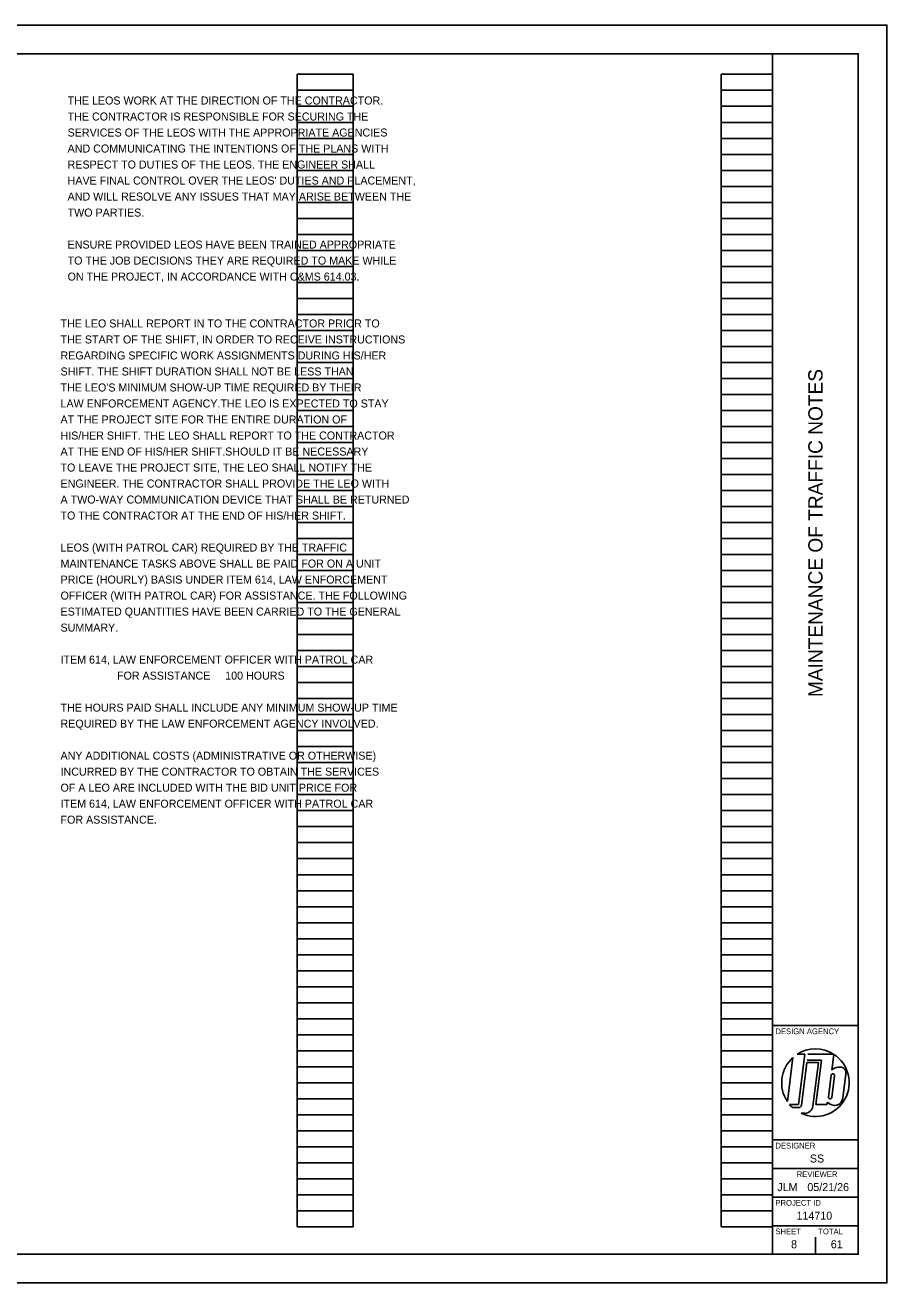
# Model space of a CAD drawing. Extents: x 0 to 34, y 0 to 22.
# Drawn here: x 18.92 to 34, y 0 to 22 of the extents above; entities that cross this region are included whole.
import ezdxf

# ---------------------------------------------------------------- set-up
doc = ezdxf.new("R2010")
doc.units = 0
for name, color, linetype in [('SH_Border', 7, 'Continuous'), ('SH_Cut_Line', 7, 'Continuous'), ('SH_Data', 7, 'Continuous'), ('SH_Text', 7, 'Continuous')]:
    doc.layers.add(name, color=color, linetype=linetype)

msp = doc.modelspace()

# ---------------------------------------------------------------- linework, layer by layer
at = {"layer": 'SH_Border'}
for p, q in [((32, 0.5), (32, 21.5)), ((32, 4.5), (33.5, 4.5)), ((32, 2.5), (33.5, 2.5)), ((32, 2), (33.5, 2)), ((32, 1.5), (33.5, 1.5)), ((32, 1), (33.5, 1))]:
    msp.add_line(p, q, dxfattribs=at)
msp.add_lwpolyline([(1.5, 21.5), (33.5, 21.5), (33.5, 0.5), (1.5, 0.5)], close=True, dxfattribs=at)
at = {"layer": 'SH_Cut_Line'}
msp.add_lwpolyline([(0, 0), (34, 0), (34, 22), (0, 22)], close=True, dxfattribs=at)
at = {"layer": 'SH_Data'}
for p, q in [((23.68, 0.98), (23.68, 21.14)), ((23.68, 21.14), (24.66, 21.14)), ((24.66, 0.98), (24.66, 21.14)), ((31.1, 0.98), (31.1, 21.14)), ((31.1, 21.14), (32, 21.14)), ((32, 0.98), (32, 21.14)), ((23.68, 20.86), (24.66, 20.86)), ((31.1, 20.86), (32, 20.86)), ((23.68, 20.58), (24.66, 20.58)), ((31.1, 20.58), (32, 20.58)), ((23.68, 20.3), (24.66, 20.3)), ((31.1, 20.3), (32, 20.3)), ((23.68, 20.02), (24.66, 20.02)), ((31.1, 20.02), (32, 20.02)), ((23.68, 19.74), (24.66, 19.74)), ((31.1, 19.74), (32, 19.74)), ((23.68, 19.46), (24.66, 19.46)), ((31.1, 19.46), (32, 19.46)), ((23.68, 19.18), (24.66, 19.18)), ((31.1, 19.18), (32, 19.18)), ((23.68, 18.9), (24.66, 18.9)), ((31.1, 18.9), (32, 18.9)), ((23.68, 18.62), (24.66, 18.62)), ((31.1, 18.62), (32, 18.62)), ((23.68, 18.34), (24.66, 18.34)), ((31.1, 18.34), (32, 18.34)), ((23.68, 18.06), (24.66, 18.06)), ((31.1, 18.06), (32, 18.06)), ((23.68, 17.78), (24.66, 17.78)), ((31.1, 17.78), (32, 17.78)), ((23.68, 17.5), (24.66, 17.5)), ((31.1, 17.5), (32, 17.5)), ((23.68, 17.22), (24.66, 17.22)), ((31.1, 17.22), (32, 17.22)), ((23.68, 16.94), (24.66, 16.94)), ((31.1, 16.94), (32, 16.94)), ((23.68, 16.66), (24.66, 16.66)), ((31.1, 16.66), (32, 16.66)), ((23.68, 16.38), (24.66, 16.38)), ((31.1, 16.38), (32, 16.38)), ((23.68, 16.1), (24.66, 16.1)), ((31.1, 16.1), (32, 16.1)), ((23.68, 15.82), (24.66, 15.82)), ((31.1, 15.82), (32, 15.82)), ((23.68, 15.54), (24.66, 15.54)), ((31.1, 15.54), (32, 15.54)), ((23.68, 15.26), (24.66, 15.26)), ((31.1, 15.26), (32, 15.26)), ((23.68, 14.98), (24.66, 14.98)), ((31.1, 14.98), (32, 14.98)), ((23.68, 14.7), (24.66, 14.7)), ((31.1, 14.7), (32, 14.7)), ((23.68, 14.42), (24.66, 14.42)), ((31.1, 14.42), (32, 14.42)), ((23.68, 14.14), (24.66, 14.14)), ((31.1, 14.14), (32, 14.14)), ((23.68, 13.86), (24.66, 13.86)), ((31.1, 13.86), (32, 13.86)), ((23.68, 13.58), (24.66, 13.58)), ((31.1, 13.58), (32, 13.58)), ((23.68, 13.3), (24.66, 13.3)), ((31.1, 13.3), (32, 13.3)), ((23.68, 13.02), (24.66, 13.02)), ((31.1, 13.02), (32, 13.02)), ((23.68, 12.74), (24.66, 12.74)), ((31.1, 12.74), (32, 12.74)), ((23.68, 12.46), (24.66, 12.46)), ((31.1, 12.46), (32, 12.46)), ((23.68, 12.18), (24.66, 12.18)), ((31.1, 12.18), (32, 12.18)), ((23.68, 11.9), (24.66, 11.9)), ((31.1, 11.9), (32, 11.9)), ((23.68, 11.62), (24.66, 11.62)), ((31.1, 11.62), (32, 11.62)), ((23.68, 11.34), (24.66, 11.34)), ((31.1, 11.34), (32, 11.34)), ((23.68, 11.06), (24.66, 11.06)), ((31.1, 11.06), (32, 11.06)), ((23.68, 10.78), (24.66, 10.78)), ((31.1, 10.78), (32, 10.78)), ((23.68, 10.5), (24.66, 10.5)), ((31.1, 10.5), (32, 10.5)), ((23.68, 10.22), (24.66, 10.22)), ((31.1, 10.22), (32, 10.22)), ((23.68, 9.94), (24.66, 9.94)), ((31.1, 9.94), (32, 9.94)), ((23.68, 9.66), (24.66, 9.66)), ((31.1, 9.66), (32, 9.66)), ((23.68, 9.38), (24.66, 9.38)), ((31.1, 9.38), (32, 9.38)), ((23.68, 9.1), (24.66, 9.1)), ((31.1, 9.1), (32, 9.1)), ((23.68, 8.82), (24.66, 8.82)), ((31.1, 8.82), (32, 8.82)), ((23.68, 8.54), (24.66, 8.54)), ((31.1, 8.54), (32, 8.54)), ((23.68, 8.26), (24.66, 8.26)), ((31.1, 8.26), (32, 8.26)), ((23.68, 7.98), (24.66, 7.98)), ((31.1, 7.98), (32, 7.98)), ((23.68, 7.7), (24.66, 7.7)), ((31.1, 7.7), (32, 7.7)), ((23.68, 7.42), (24.66, 7.42)), ((31.1, 7.42), (32, 7.42)), ((23.68, 7.14), (24.66, 7.14)), ((31.1, 7.14), (32, 7.14)), ((23.68, 6.86), (24.66, 6.86)), ((31.1, 6.86), (32, 6.86)), ((23.68, 6.58), (24.66, 6.58)), ((31.1, 6.58), (32, 6.58)), ((23.68, 6.3), (24.66, 6.3)), ((31.1, 6.3), (32, 6.3)), ((23.68, 6.02), (24.66, 6.02)), ((31.1, 6.02), (32, 6.02)), ((23.68, 5.74), (24.66, 5.74)), ((31.1, 5.74), (32, 5.74)), ((23.68, 5.46), (24.66, 5.46)), ((31.1, 5.46), (32, 5.46)), ((23.68, 5.18), (24.66, 5.18)), ((31.1, 5.18), (32, 5.18)), ((23.68, 4.9), (24.66, 4.9)), ((31.1, 4.9), (32, 4.9)), ((23.68, 4.62), (24.66, 4.62)), ((31.1, 4.62), (32, 4.62)), ((23.68, 4.34), (24.66, 4.34)), ((31.1, 4.34), (32, 4.34)), ((23.68, 4.06), (24.66, 4.06)), ((31.1, 4.06), (32, 4.06)), ((32.432, 3.998), (32.567, 3.998)), ((32.567, 3.998), (32.456, 3.118)), ((32.617, 4), (33.065, 4)), ((33.07, 3.996), (33.035, 3.72)), ((23.68, 3.78), (24.66, 3.78)), ((31.1, 3.78), (32, 3.78)), ((32.356, 3.94), (32.259, 3.171)), ((32.504, 3.104), (32.599, 3.855)), ((32.599, 3.855), (32.801, 3.855)), ((32.856, 3.896), (32.604, 3.896)), ((32.801, 3.855), (32.704, 3.089)), ((32.758, 3.118), (32.856, 3.896)), ((33.024, 3.631), (32.976, 3.25)), ((33.036, 3.243), (33.084, 3.624)), ((33.283, 3.648), (33.231, 3.237)), ((23.68, 3.5), (24.66, 3.5)), ((31.1, 3.5), (32, 3.5)), ((32.75, 3.5), (32.75, 3.5)), ((23.68, 3.22), (24.66, 3.22)), ((31.1, 3.22), (32, 3.22)), ((32.456, 3.118), (32.299, 3.118)), ((32.947, 3.118), (32.758, 3.118)), ((32.964, 3.161), (32.947, 3.118)), ((23.68, 2.94), (24.66, 2.94)), ((31.1, 2.94), (32, 2.94)), ((32.347, 3.068), (32.462, 3.068)), ((32.564, 2.966), (32.498, 2.966)), ((23.68, 2.66), (24.66, 2.66)), ((31.1, 2.66), (32, 2.66)), ((23.68, 2.38), (24.66, 2.38)), ((31.1, 2.38), (32, 2.38)), ((23.68, 2.1), (24.66, 2.1)), ((31.1, 2.1), (32, 2.1)), ((23.68, 1.82), (24.66, 1.82)), ((31.1, 1.82), (32, 1.82)), ((23.68, 1.54), (24.66, 1.54)), ((31.1, 1.54), (32, 1.54)), ((23.68, 1.26), (24.66, 1.26)), ((31.1, 1.26), (32, 1.26)), ((23.68, 0.98), (24.66, 0.98)), ((31.1, 0.98), (32, 0.98)), ((32.375, 0.675), (32.375, 0.675)), ((32.75, 0.5), (32.75, 0.8))]:
    msp.add_line(p, q, dxfattribs=at)
for centre, radius, start, end in [((32.75, 3.5), 0.591, 57.726, 122.5688), ((32.75, 3.5), 0.591, 244.7646, 57.1575), ((32.75, 3.5), 0.591, 131.8253, 213.7822), ((33.17, 3.586), 0.19, 105.9444, 135.0487), ((33.164, 3.6), 0.175, 66.6782, 105.4185), ((33.177, 3.669), 0.108, 349.2072, 58.7163), ((33.054, 3.628), 0.0301, 352.3298, 173.2777), ((32.75, 3.5), 0.591, 220.2786, 227.0158), ((32.462, 3.109), 0.0417, 270, 352.8038), ((32.564, 3.106), 0.141, 270, 352.8038), ((33.081, 3.255), 0.151, 218.6264, 353.0883), ((33.006, 3.246), 0.0301, 172.3335, 353.274)]:
    msp.add_arc(centre, radius, start, end, dxfattribs=at)

# ---------------------------------------------------------------- texts
msp.add_text('MAINTENANCE OF TRAFFIC NOTES', height=0.25, rotation=90, dxfattribs=at).set_placement((32.875, 10.247))
for s, height, p in [('DESIGN AGENCY', 0.1, (32.05, 4.35)), ('DESIGNER', 0.1, (32.05, 2.35)), ('SS', 0.14, (32.653, 2.105)), ('REVIEWER', 0.1, (32.422, 1.85)), ('JLM', 0.14, (32.083, 1.605)), ('05/21/26', 0.14, (32.609, 1.605)), ('PROJECT ID', 0.1, (32.05, 1.35)), ('114710', 0.14, (32.419, 1.105)), ('SHEET', 0.1, (32.05, 0.85)), ('TOTAL', 0.1, (32.8, 0.85)), ('8', 0.14, (32.324, 0.605)), ('61', 0.14, (33.019, 0.605))]:
    msp.add_text(s, height=height, dxfattribs=at).set_placement(p)
at = {"layer": 'SH_Text'}
for s, p in [('THE LEOS WORK AT THE DIRECTION OF THE CONTRACTOR.', (19.664, 20.612)), ('THE CONTRACTOR IS RESPONSIBLE FOR SECURING THE', (19.664, 20.332)), ('SERVICES OF THE LEOS WITH THE APPROPRIATE AGENCIES', (19.664, 20.052)), ('AND COMMUNICATING THE INTENTIONS OF THE PLANS WITH', (19.664, 19.772)), ('RESPECT TO DUTIES OF THE LEOS. THE ENGINEER SHALL', (19.664, 19.492)), ("HAVE FINAL CONTROL OVER THE LEOS' DUTIES AND PLACEMENT,", (19.664, 19.212)), ('AND WILL RESOLVE ANY ISSUES THAT MAY ARISE BETWEEN THE', (19.664, 18.932)), ('TWO PARTIES.', (19.664, 18.652)), ('ENSURE PROVIDED LEOS HAVE BEEN TRAINED APPROPRIATE', (19.664, 18.092)), ('TO THE JOB DECISIONS THEY ARE REQUIRED TO MAKE WHILE', (19.664, 17.812)), ('ON THE PROJECT, IN ACCORDANCE WITH C&MS 614.03.', (19.664, 17.532)), ('THE LEO SHALL REPORT IN TO THE CONTRACTOR PRIOR TO', (19.54, 16.712)), ('THE START OF THE SHIFT, IN ORDER TO RECEIVE INSTRUCTIONS', (19.54, 16.432)), ('REGARDING SPECIFIC WORK ASSIGNMENTS DURING HIS/HER', (19.54, 16.152)), ('SHIFT. THE SHIFT DURATION SHALL NOT BE LESS THAN', (19.54, 15.872)), ("THE LEO'S MINIMUM SHOW-UP TIME REQUIRED BY THEIR", (19.54, 15.592)), ('LAW ENFORCEMENT AGENCY.THE LEO IS EXPECTED TO STAY', (19.54, 15.312)), ('AT THE PROJECT SITE FOR THE ENTIRE DURATION OF', (19.54, 15.032)), ('HIS/HER SHIFT. THE LEO SHALL REPORT TO THE CONTRACTOR', (19.54, 14.752)), ('AT THE END OF HIS/HER SHIFT.SHOULD IT BE NECESSARY', (19.54, 14.472)), ('TO LEAVE THE PROJECT SITE, THE LEO SHALL NOTIFY THE', (19.54, 14.192)), ('ENGINEER. THE CONTRACTOR SHALL PROVIDE THE LEO WITH', (19.54, 13.912)), ('A TWO-WAY COMMUNICATION DEVICE THAT SHALL BE RETURNED', (19.54, 13.632)), ('TO THE CONTRACTOR AT THE END OF HIS/HER SHIFT.', (19.54, 13.352)), ('LEOS (WITH PATROL CAR) REQUIRED BY THE TRAFFIC', (19.54, 12.792)), ('MAINTENANCE TASKS ABOVE SHALL BE PAID FOR ON A UNIT', (19.54, 12.512)), ('PRICE (HOURLY) BASIS UNDER ITEM 614, LAW ENFORCEMENT', (19.54, 12.232)), ('OFFICER (WITH PATROL CAR) FOR ASSISTANCE. THE FOLLOWING', (19.54, 11.952)), ('ESTIMATED QUANTITIES HAVE BEEN CARRIED TO THE GENERAL', (19.54, 11.672)), ('SUMMARY.', (19.54, 11.392)), ('ITEM 614, LAW ENFORCEMENT OFFICER WITH PATROL CAR', (19.54, 10.832)), ('                   FOR ASSISTANCE     100 HOURS', (19.54, 10.552)), ('THE HOURS PAID SHALL INCLUDE ANY MINIMUM SHOW-UP TIME', (19.54, 9.992)), ('REQUIRED BY THE LAW ENFORCEMENT AGENCY INVOLVED.', (19.54, 9.712)), ('ANY ADDITIONAL COSTS (ADMINISTRATIVE OR OTHERWISE)', (19.54, 9.152)), ('INCURRED BY THE CONTRACTOR TO OBTAIN THE SERVICES', (19.54, 8.872)), ('OF A LEO ARE INCLUDED WITH THE BID UNIT PRICE FOR', (19.54, 8.592)), ('ITEM 614, LAW ENFORCEMENT OFFICER WITH PATROL CAR', (19.54, 8.312)), ('FOR ASSISTANCE.', (19.54, 8.032))]:
    msp.add_text(s, height=0.14, dxfattribs=at).set_placement(p)

doc.saveas('drawing.dxf')
